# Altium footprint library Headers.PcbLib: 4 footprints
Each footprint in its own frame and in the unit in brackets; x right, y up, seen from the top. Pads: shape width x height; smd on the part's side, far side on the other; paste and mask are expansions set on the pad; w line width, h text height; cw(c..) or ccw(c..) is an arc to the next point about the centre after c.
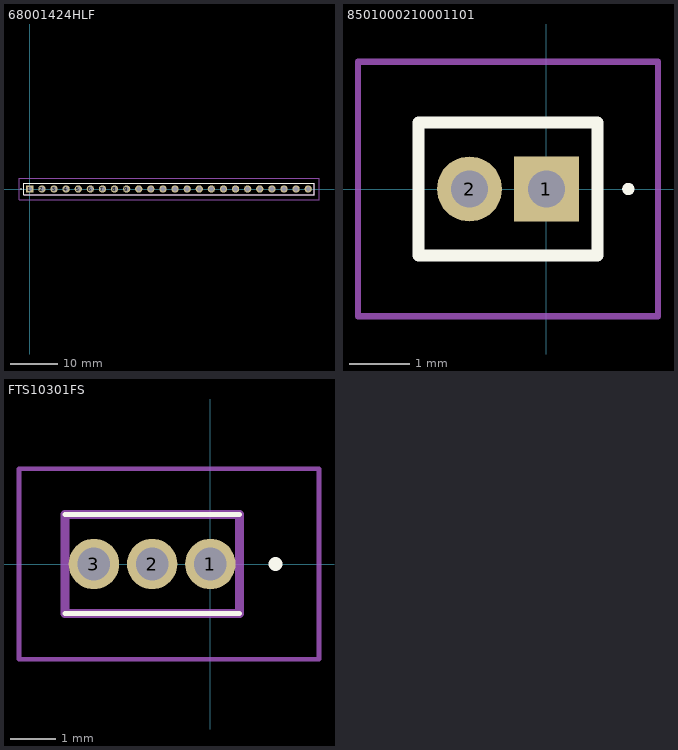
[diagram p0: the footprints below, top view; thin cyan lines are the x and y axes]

## 68001424HLF [mm]
pads (24):
  rect 1.53x1.53 hole 1.02: 1(0,0)
  round 1.53 hole 1.02: 2(2.54,0) 3(5.08,0) 4(7.62,0) 5(10.16,0) 6(12.7,0) 7(15.24,0) 8(17.78,0) 9(20.32,0) 10(22.86,0) 11(25.4,0) 12(27.94,0) 13(30.48,0) 14(33.02,0) 15(35.56,0) 16(38.1,0) 17(40.64,0) 18(43.18,0) 19(45.72,0) 20(48.26,0) 21(50.8,0) 22(53.34,0) 23(55.88,0) 24(58.42,0)
Top Overlay:
  lines w0.1: -1.9,0 cw(c-1.85,0) -1.8,0 cw(c-1.85,0) -1.9,0
  lines w0.2: -1.27,-1.205 59.69,-1.205 59.69,1.205 -1.27,1.205 -1.27,-1.205
Mechanical 13:
  lines w0.1: -1.27,-1.205 59.69,-1.205 59.69,1.205 -1.27,1.205 -1.27,-1.205
Mechanical 15:
  lines w0.1: -2.27,-2.205 60.69,-2.205 60.69,2.205 -2.27,2.205 -2.27,-2.205
3D body "68001-424HLF--3DModel-STEP-56544.STEP": height 8.38, standoff -3.05, extent -1.27,-1.205 59.69,1.205

## 8501000210001101 [mm]
pads (2):
  rect 1.07x1.07 hole 0.61: 1(0,0)
  round 1.07 hole 0.61: 2(-1.27,0)
Top Overlay:
  lines w0.1: 1.3,0 cw(c1.35,0) 1.4,0 cw(c1.35,0) 1.3,0
  lines w0.2: -2.11,-1.1 -2.11,1.1 0.84,1.1 0.84,-1.1 -2.11,-1.1
Mechanical 13:
  lines w0.1: -2.11,-1.1 -2.11,1.1 0.84,1.1 0.84,-1.1 -2.11,-1.1
Mechanical 15:
  lines w0.1: -3.11,-2.1 1.84,-2.1 1.84,2.1 -3.11,2.1 -3.11,-2.1
3D body "850-10-002-10-001101.stp": height 5.16, standoff -2.94, extent -2.115,-1.1 0.835,1.1

## FTS10301FS [mm]
pads (3):
  round 1.1 hole 0.71: 1(0,0) 2(-1.27,0) 3(-2.54,0)
Top Overlay:
  lines w0.1: -3.175,-1.08 0.635,-1.08 ; -3.175,1.08 0.635,1.08
  lines w0.2: 1.37,0 ccw(c1.42,0) 1.47,0 ccw(c1.42,0) 1.37,0
Mechanical 13:
  lines w0.2: -3.175,-1.08 -3.175,1.08 0.635,1.08 0.635,-1.08 -3.175,-1.08
Mechanical 15:
  lines w0.1: -4.175,-2.08 -4.175,2.08 2.37,2.08 2.37,-2.08 -4.175,-2.08
3D body "FTS-103-01-F-S.stp": height 4.01, standoff -5, extent -3.175,-1.08 0.635,1.08

## PCBComponent_1 [mil]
